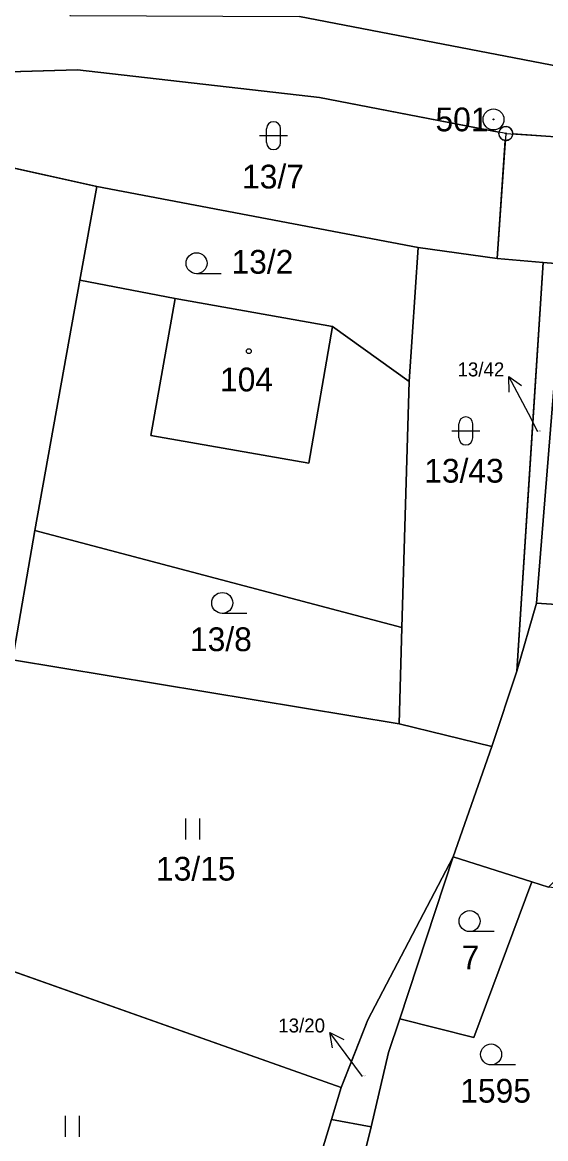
# Model space of a CAD drawing. Extents: x -760642 to -757221, y -1092371 to -1088855.
# Drawn here: x -758998.7 to -758961.3, y -1089902.3 to -1089822.5 of the extents above; entities that cross this region are included whole.
import ezdxf

# ---------------------------------------------------------------- set-up
doc = ezdxf.new("R2010")
doc.units = 0
for name, color, linetype in [('Vrstva 1', 7, 'Continuous'), ('Vrstva 16', 7, 'Continuous'), ('Vrstva 17', 7, 'Continuous'), ('Vrstva 18', 7, 'Continuous'), ('Vrstva 19', 7, 'Continuous'), ('Vrstva 24', 7, 'Continuous'), ('Vrstva 25', 7, 'Continuous'), ('Vrstva 26', 7, 'Continuous'), ('Vrstva 4', 7, 'Continuous')]:
    doc.layers.add(name, color=color, linetype=linetype)

msp = doc.modelspace()

# ---------------------------------------------------------------- linework, layer by layer
at = {"layer": 'Vrstva 1'}
for p, q in [((-758940.36, -1089829.46), (-758978.87, -1089822.04)), ((-758994.74, -1089825.85), (-759003.66, -1089826.12)), ((-758977.43, -1089827.83), (-758994.74, -1089825.85)), ((-759021.58, -1089827.93), (-758993.37, -1089834.2)), ((-758964.11, -1089830.4), (-758977.43, -1089827.83)), ((-758964.11, -1089830.4), (-758964.74, -1089839.36)), ((-758964.11, -1089830.4), (-758952.79, -1089831.19)), ((-758993.37, -1089834.2), (-758994.57, -1089840.9)), ((-758993.37, -1089834.2), (-758970.39, -1089838.57)), ((-758970.39, -1089838.57), (-758971.02, -1089848.16)), ((-758970.39, -1089838.57), (-758964.74, -1089839.36)), ((-758961.45, -1089839.63), (-758964.74, -1089839.36)), ((-758961.45, -1089839.63), (-758963.31, -1089868.89)), ((-758959.96, -1089839.75), (-758961.91, -1089864.02)), ((-758959.96, -1089839.75), (-758961.45, -1089839.63)), ((-758994.57, -1089840.9), (-758997.8, -1089858.81)), ((-758987.77, -1089842.21), (-758994.57, -1089840.9)), ((-758987.77, -1089842.21), (-758976.5, -1089844.22)), ((-758976.5, -1089844.22), (-758971.02, -1089848.16)), ((-758971.02, -1089848.16), (-758971.54, -1089865.75)), ((-758997.8, -1089858.81), (-758999.39, -1089868.07)), ((-758997.8, -1089858.81), (-758971.54, -1089865.75)), ((-758961.91, -1089864.02), (-758963.31, -1089868.89)), ((-758951.2, -1089864.74), (-758961.91, -1089864.02)), ((-758971.54, -1089865.75), (-758971.74, -1089872.65)), ((-758971.74, -1089872.65), (-758999.39, -1089868.07)), ((-758963.31, -1089868.89), (-758965.11, -1089874.27)), ((-758971.74, -1089872.65), (-758965.11, -1089874.27)), ((-758967.88, -1089882.17), (-758965.11, -1089874.27)), ((-758973.98, -1089893.84), (-758967.88, -1089882.17)), ((-758967.88, -1089882.17), (-758971.7, -1089893.76)), ((-758962.25, -1089883.95), (-758967.88, -1089882.17)), ((-758962.25, -1089883.95), (-758966.39, -1089895.11)), ((-758962.25, -1089883.95), (-758961.05, -1089884.33)), ((-759006.34, -1089887.89), (-758975.89, -1089898.68)), ((-758975.89, -1089898.68), (-758973.98, -1089893.84)), ((-758971.7, -1089893.76), (-758972.49, -1089896.18)), ((-758971.7, -1089893.76), (-758966.39, -1089895.11)), ((-758972.49, -1089896.18), (-758973.75, -1089901.48)), ((-758976.58, -1089900.97), (-758975.89, -1089898.68)), ((-758979.65, -1089911.07), (-758976.58, -1089900.97)), ((-758976.58, -1089900.97), (-758973.75, -1089901.48)), ((-758973.75, -1089901.48), (-758974.24, -1089903.51))]:
    msp.add_line(p, q, dxfattribs=at)
at = {"layer": 'Vrstva 16'}
for p, q in [((-758962.49, -1089850.45), (-758963.885, -1089847.794)), ((-758961.81, -1089851.75), (-758962.49, -1089850.45)), ((-758974.9, -1089897.15), (-758976.693, -1089894.744)), ((-758974.35, -1089897.88), (-758974.9, -1089897.15))]:
    msp.add_line(p, q, dxfattribs=at)
for points in [[(-758963.863, -1089848.912), (-758963.885, -1089847.794), (-758962.977, -1089848.447)], [(-758976.496, -1089895.845), (-758976.693, -1089894.744), (-758975.694, -1089895.248)]]:
    msp.add_lwpolyline(points, dxfattribs=at)
at = {"layer": 'Vrstva 24'}
for centre, radius in [((-758964.99, -1089829.4), 0.75), ((-758964.99, -1089829.4), 0.0327), ((-758964.11, -1089830.4), 0.5), ((-758964.11, -1089830.4), 0.0327)]:
    msp.add_circle(centre, radius, dxfattribs=at)
at = {"layer": 'Vrstva 25'}
for p, q in [((-758981.22, -1089831.06), (-758981.22, -1089830.06)), ((-758980.22, -1089831.06), (-758980.22, -1089830.06)), ((-758981.72, -1089830.56), (-758979.72, -1089830.56)), ((-758984.48, -1089840.44), (-758986.23, -1089840.44)), ((-758967.47, -1089852.19), (-758967.47, -1089851.19)), ((-758966.47, -1089852.19), (-758966.47, -1089851.19)), ((-758967.97, -1089851.69), (-758965.97, -1089851.69)), ((-758982.64, -1089864.75), (-758984.39, -1089864.75)), ((-758987.017, -1089879.435), (-758987.017, -1089880.935)), ((-758985.995, -1089880.935), (-758985.995, -1089879.435)), ((-758964.95, -1089887.52), (-758966.7, -1089887.52)), ((-758963.41, -1089897.06), (-758965.16, -1089897.06)), ((-758995.627, -1089900.715), (-758995.627, -1089902.215)), ((-758994.605, -1089902.215), (-758994.605, -1089900.715))]:
    msp.add_line(p, q, dxfattribs=at)
for centre, radius in [((-758986.23, -1089839.69), 0.75), ((-758982.49, -1089845.98), 0.175), ((-758984.39, -1089864), 0.75), ((-758966.7, -1089886.77), 0.75), ((-758965.16, -1089896.31), 0.75)]:
    msp.add_circle(centre, radius, dxfattribs=at)
for centre, start, end in [((-758980.72, -1089830.06), 0, 180), ((-758980.72, -1089831.06), 180, 0), ((-758966.97, -1089851.19), 0, 180), ((-758966.97, -1089852.19), 180, 0)]:
    msp.add_arc(centre, 0.5, start, end, dxfattribs=at)
at = {"layer": 'Vrstva 26'}
for points in [[(-759049.32, -1089817.46), (-759021.58, -1089827.93), (-759003.66, -1089826.12), (-758994.74, -1089825.85), (-758977.43, -1089827.83), (-758964.601, -1089830.305)], [(-758977.118, -1089818.836), (-758981.19, -1089818.61), (-758994.11, -1089817.55), (-758994.67, -1089819.64), (-758995.29, -1089821.97), (-758978.87, -1089822.04), (-758940.36, -1089829.46), (-758915.94, -1089831.98), (-758899.04, -1089835.16), (-758894.95, -1089837.25), (-758873.57, -1089841.83), (-758872.87, -1089838.03), (-758894.48, -1089831.19), (-758895.18, -1089829.55), (-758908.4, -1089826.64), (-758937.97, -1089820.13), (-758956.38, -1089819.99), (-758977.118, -1089818.836)], [(-758963.611, -1089830.435), (-758952.79, -1089831.19), (-758949.17, -1089831.31), (-758943.53, -1089831.74), (-758937.22, -1089832.05), (-758924.87, -1089832.81), (-758919.62, -1089832.74), (-758917.76, -1089837.18), (-758916.16, -1089832.7), (-758914.44, -1089833.07), (-758894.95, -1089837.25), (-758899.04, -1089835.16), (-758915.94, -1089831.98), (-758940.36, -1089829.46), (-758978.87, -1089822.04)], [(-758997.8, -1089858.81), (-758994.57, -1089840.9), (-758993.37, -1089834.2), (-759021.58, -1089827.93), (-759040.51, -1089825.71), (-759046.54, -1089859.18), (-759006.56, -1089866.72), (-758999.39, -1089868.07), (-758997.8, -1089858.81)], [(-758964.601, -1089830.305), (-758977.43, -1089827.83), (-758994.74, -1089825.85), (-759003.66, -1089826.12), (-759021.58, -1089827.93), (-758993.37, -1089834.2), (-758970.39, -1089838.57), (-758964.74, -1089839.36), (-758964.145, -1089830.899)], [(-758964.145, -1089830.899), (-758964.74, -1089839.36), (-758961.45, -1089839.63), (-758959.96, -1089839.75), (-758961.91, -1089864.02), (-758951.2, -1089864.74), (-758950.3, -1089848.25), (-758949.79, -1089839.63), (-758953.24, -1089839.35), (-758952.79, -1089831.19), (-758963.611, -1089830.435)], [(-758993.37, -1089834.2), (-758994.57, -1089840.9), (-758987.77, -1089842.21), (-758976.5, -1089844.22), (-758971.02, -1089848.16), (-758970.39, -1089838.57), (-758993.37, -1089834.2)], [(-758962.176, -1089851.05), (-758961.45, -1089839.63), (-758964.74, -1089839.36), (-758970.39, -1089838.57), (-758971.02, -1089848.16), (-758971.54, -1089865.75), (-758971.74, -1089872.65), (-758965.11, -1089874.27), (-758963.31, -1089868.89), (-758962.176, -1089851.05)], [(-758962.176, -1089851.05), (-758963.31, -1089868.89), (-758961.91, -1089864.02), (-758959.96, -1089839.75), (-758961.45, -1089839.63), (-758962.176, -1089851.05)], [(-758989.49, -1089852.02), (-758987.77, -1089842.21), (-758994.57, -1089840.9), (-758997.8, -1089858.81), (-758971.54, -1089865.75), (-758971.02, -1089848.16), (-758976.5, -1089844.22), (-758978.19, -1089853.99), (-758989.49, -1089852.02)], [(-758987.77, -1089842.21), (-758989.49, -1089852.02), (-758978.19, -1089853.99), (-758976.5, -1089844.22), (-758987.77, -1089842.21)], [(-758999.39, -1089868.07), (-758971.74, -1089872.65), (-758971.54, -1089865.75), (-758997.8, -1089858.81), (-758999.39, -1089868.07)], [(-758956.94, -1089880.32), (-758953.08, -1089876.55), (-758951.34, -1089865.62), (-758951.2, -1089864.74), (-758961.91, -1089864.02), (-758963.31, -1089868.89), (-758965.11, -1089874.27), (-758967.88, -1089882.17), (-758962.25, -1089883.95), (-758961.05, -1089884.33), (-758956.94, -1089880.32)], [(-758975.153, -1089896.811), (-758973.98, -1089893.84), (-758967.88, -1089882.17), (-758965.11, -1089874.27), (-758971.74, -1089872.65), (-758999.39, -1089868.07), (-759006.34, -1089887.89), (-758975.89, -1089898.68), (-758975.153, -1089896.811)], [(-758975.153, -1089896.811), (-758975.89, -1089898.68), (-758976.58, -1089900.97), (-758973.75, -1089901.48), (-758972.49, -1089896.18), (-758971.7, -1089893.76), (-758967.88, -1089882.17), (-758973.98, -1089893.84), (-758975.153, -1089896.811)], [(-758971.7, -1089893.76), (-758966.39, -1089895.11), (-758962.25, -1089883.95), (-758967.88, -1089882.17), (-758971.7, -1089893.76)], [(-758972.49, -1089896.18), (-758973.75, -1089901.48), (-758974.24, -1089903.51), (-758963.62, -1089905.81), (-758961.07, -1089906.28), (-758959.04, -1089899.19), (-758957.66, -1089894.38), (-758957.24, -1089892), (-758955.77, -1089884.91), (-758961.05, -1089884.33), (-758962.25, -1089883.95), (-758966.39, -1089895.11), (-758971.7, -1089893.76), (-758972.49, -1089896.18)], [(-758975.44, -1089920.9), (-758973.79, -1089916.73), (-758979.65, -1089911.07), (-758976.58, -1089900.97), (-758975.89, -1089898.68), (-759006.34, -1089887.89), (-759013.29, -1089907.7), (-758975.44, -1089920.9)], [(-758976.58, -1089900.97), (-758979.65, -1089911.07), (-758973.79, -1089916.73), (-758970.35, -1089920.05), (-758963.62, -1089905.81), (-758974.24, -1089903.51), (-758973.75, -1089901.48), (-758976.58, -1089900.97)]]:
    msp.add_lwpolyline(points, dxfattribs=at)
for start, end in [(169.07938, 180), (180, 265.97801), (0, 169.07938), (265.97801, 356.00792), (356.00792, 0)]:
    msp.add_arc((-758964.11, -1089830.4), 0.5, start, end, dxfattribs=at)
at = {"layer": 'Vrstva 4'}
for p, q in [((-758989.49, -1089852.02), (-758987.77, -1089842.21)), ((-758976.5, -1089844.22), (-758978.19, -1089853.99)), ((-758978.19, -1089853.99), (-758989.49, -1089852.02))]:
    msp.add_line(p, q, dxfattribs=at)

# ---------------------------------------------------------------- texts
at = {"layer": 'Vrstva 16'}
for s, p in [('13/42', (-758967.563, -1089847.79)), ('13/20', (-758980.385, -1089894.74))]:
    msp.add_text(s, height=1, dxfattribs=at).set_placement(p)
at = {"layer": 'Vrstva 17'}
msp.add_text('501', height=1.7, dxfattribs=at).set_placement((-758969.141, -1089830.25))
at = {"layer": 'Vrstva 18'}
for s, height, p in [('13/7', 1.7, (-758982.975, -1089834.34)), ('13/2', 1.7, (-758983.73, -1089840.44)), ('13/42', 0.1, (-758961.944, -1089851.75)), ('13/43', 1.7, (-758969.946, -1089855.39)), ('13/8', 1.7, (-758986.7, -1089867.45)), ('13/15', 1.7, (-758989.13, -1089883.87)), ('7', 1.7, (-758967.272, -1089890.22)), ('13/20', 0.1, (-758974.484, -1089897.88)), ('1595', 1.7, (-758967.368, -1089899.76))]:
    msp.add_text(s, height=height, dxfattribs=at).set_placement(p)
at = {"layer": 'Vrstva 19'}
msp.add_text('104', height=1.7, dxfattribs=at).set_placement((-758984.55, -1089848.86))

doc.saveas('drawing.dxf')
